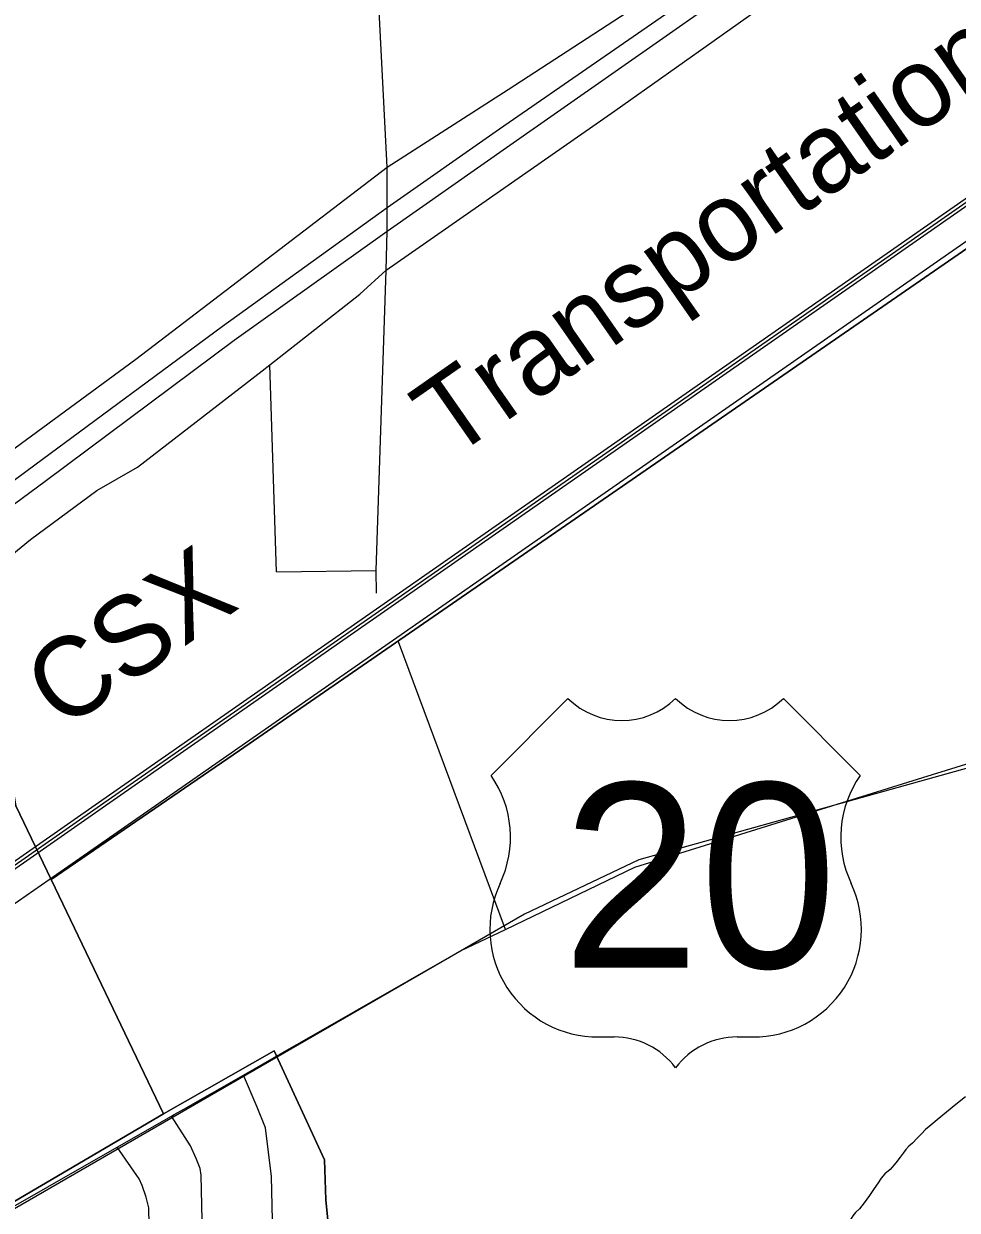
# Model space of a CAD drawing. Extents: x 0 to 44.3, y 0 to 22.
# Drawn here: x 2.7 to 3.367, y 16.867 to 17.715 of the extents above; entities that cross this region are included whole.
import ezdxf

# ---------------------------------------------------------------- set-up
doc = ezdxf.new("R2010")
doc.units = 0
for name, color, linetype in [('GM_X_City_Street', 7, 'Continuous'), ('GM_X_Corporation', 7, 'Continuous'), ('GM_X_County_Road', 7, 'Continuous'), ('GM_X_Minor_River', 7, 'Continuous'), ('GM_X_Rail_Line', 7, 'Continuous'), ('GM_X_Rail_Line_Text', 7, 'Continuous'), ('GM_X_State_Route', 7, 'Continuous'), ('GM_X_US_Location', 7, 'Continuous'), ('GM_X_US_Route', 7, 'Continuous'), ('GM_X_US_Shield', 7, 'Continuous')]:
    doc.layers.add(name, color=color, linetype=linetype)

msp = doc.modelspace()

# ---------------------------------------------------------------- linework, layer by layer
at = {"layer": 'GM_X_City_Street'}
for p, q in [((2.88029, 17.32334), (2.87573, 17.47119)), ((2.88029, 17.32334), (2.95151, 17.32441)), ((3.04389, 17.06804), (2.96757, 17.27355))]:
    msp.add_line(p, q, dxfattribs=at)
for points in [[(2.95187, 17.30811), (2.95151, 17.32441), (2.95874, 17.53886), (2.9594, 17.56671), (2.9594, 17.58355), (2.9594, 17.61233), (2.94193, 17.95676), (2.94104, 18.04987), (2.9488, 18.40637)], [(2.88377, 16.39702), (2.88228, 16.44641), (2.88116, 16.49123), (2.88085, 16.51724), (2.87975, 16.60759), (2.8797, 16.61126), (2.8775, 16.73361), (2.87748, 16.73471), (2.87809, 16.83955), (2.87673, 16.89154), (2.87266, 16.92638), (2.86669, 16.94107), (2.85676, 16.96405)], [(2.83536, 16.49119), (2.83285, 16.60705), (2.83014, 16.73191), (2.82665, 16.89244), (2.826, 16.89737), (2.82305, 16.90437), (2.81901, 16.91356), (2.80533, 16.93467)], [(2.79671, 16.49113), (2.78916, 16.86929), (2.78734, 16.87677), (2.7844, 16.88524), (2.78232, 16.89004), (2.76664, 16.91258)]]:
    msp.add_lwpolyline(points, dxfattribs=at)
at = {"layer": 'GM_X_Corporation'}
for points in [[(2.1, 19.02359), (2.1, 17.10272), (2.42877, 17.10648), (2.43353, 16.7048), (2.48712, 16.74746), (2.538, 16.78285), (2.79959, 16.93639), (2.71939, 17.10372), (2.69423, 17.15622), (2.62885, 17.5345), (2.62195, 17.86014), (2.59129, 17.85933), (2.5903, 17.98005), (2.60997, 17.98184), (2.60886, 18.21609), (2.59413, 18.21561), (2.59648, 18.31022), (2.59485, 18.40033), (2.69521, 18.39964), (2.69153, 18.60222), (2.17836, 19.1187), (2.14854, 19.0743)], [(2.1, 17.10272), (2.1, 14.89093), (2.15007, 14.89026), (2.15156, 14.77637), (2.41649, 14.78874), (2.41538, 14.81071), (2.41193, 15.22884), (3.14802, 15.25348), (3.1444, 15.75035), (3.14473, 15.8221), (3.08208, 15.81996), (3.0702, 16.39939), (3.07041, 16.48664), (2.92509, 16.48168), (2.92043, 16.69656), (2.91923, 16.83909), (2.91562, 16.87504), (2.91478, 16.90347), (2.87873, 16.98136), (2.79959, 16.93639), (2.538, 16.78285), (2.48712, 16.74746), (2.43353, 16.7048), (2.42877, 17.10648)]]:
    msp.add_lwpolyline(points, close=True, dxfattribs=at)
for points in [[(2.62195, 17.86014), (2.62885, 17.5345), (2.69423, 17.15622), (2.71939, 17.10372), (2.85409, 17.19593), (3.47183, 17.62229), (3.84891, 17.88417)], [(3.84891, 17.88417), (3.47183, 17.62229), (2.85409, 17.19593), (2.71939, 17.10372), (2.79959, 16.93639), (2.87873, 16.98136), (2.91478, 16.90347), (2.91562, 16.87504), (2.91923, 16.83909), (2.92043, 16.69656), (2.92509, 16.48168), (3.07041, 16.48664), (3.0702, 16.39939), (3.08208, 15.81996), (3.14473, 15.8221), (3.1444, 15.75035), (3.60768, 15.75757), (3.60129, 15.98668), (3.6481, 15.9878), (3.64433, 16.10299), (3.96366, 16.11374), (4.24297, 16.33163)]]:
    msp.add_lwpolyline(points, dxfattribs=at)
at = {"layer": 'GM_X_County_Road'}
for points in [[(2.64682, 17.37774), (2.78002, 17.47526), (2.9594, 17.61233), (3.04577, 17.66789), (3.24836, 17.79983)], [(2.66847, 17.31708), (2.70468, 17.34646), (2.75217, 17.38143), (2.78106, 17.39808), (2.87021, 17.46686), (2.87573, 17.47119), (2.94001, 17.52169), (2.95874, 17.53886), (3.12202, 17.65265), (3.27527, 17.76142), (3.30285, 17.78047), (3.31643, 17.78986)]]:
    msp.add_lwpolyline(points, dxfattribs=at)
at = {"layer": 'GM_X_Minor_River'}
for points in [[(3.37234, 16.94848), (3.36561, 16.94304), (3.35215, 16.93216), (3.34767, 16.92828), (3.34393, 16.92518)], [(3.34393, 16.92518), (3.34096, 16.92208), (3.33798, 16.91899), (3.33463, 16.91551), (3.33202, 16.91318), (3.32978, 16.91086), (3.32794, 16.90817), (3.32571, 16.90547), (3.32275, 16.90124), (3.31867, 16.89661), (3.31493, 16.8935), (3.31233, 16.89041), (3.31012, 16.88696), (3.30716, 16.8831), (3.30384, 16.8781), (3.30014, 16.87272), (3.29681, 16.86848), (3.29382, 16.86577), (3.29197, 16.86345), (3.29087, 16.86153), (3.28865, 16.85846), (3.28643, 16.85538), (3.28643, 16.85538), (3.28644, 16.855)]]:
    msp.add_lwpolyline(points, dxfattribs=at)
at = {"layer": 'GM_X_Rail_Line'}
for points in [[(5.03994, 18.12339), (4.88582, 17.82603), (4.85215, 17.78603), (4.65574, 17.58324), (4.63259, 17.56921), (3.85279, 17.33195), (3.39071, 17.18793), (3.13922, 17.11763), (3.05755, 17.07901), (2.5475, 16.78444), (2.47772, 16.74057), (2.40462, 16.66842), (2.31181, 16.57815), (2.1, 16.36664)], [(2.1, 16.67388), (2.15394, 16.71136), (2.72349, 17.1075), (3.49807, 17.64675), (4.11147, 18.07403)], [(2.1, 16.70485), (2.10477, 16.70818), (2.37473, 16.89595), (2.52212, 16.99726), (2.7533, 17.15857), (2.93608, 17.28602), (3.53153, 17.70081), (3.67855, 17.8033)], [(2.1, 16.70202), (2.1061, 16.70628), (2.37606, 16.89405), (2.52344, 16.99535), (2.75464, 17.15667), (2.93742, 17.28412), (3.53286, 17.69891), (3.67991, 17.80142)], [(2.1, 16.69919), (2.10744, 16.70438), (2.37739, 16.89214), (2.52477, 16.99345), (2.75597, 17.15477), (2.93875, 17.28222), (3.53419, 17.69701), (3.68127, 17.79954)]]:
    msp.add_lwpolyline(points, dxfattribs=at)
at = {"layer": 'GM_X_State_Route'}
for points in [[(2.59773, 17.31844), (2.70783, 17.39981), (2.84185, 17.49896), (2.9594, 17.58355), (3.03968, 17.63975), (3.18447, 17.74008), (3.35307, 17.85775), (3.41635, 17.90169), (3.50141, 17.96143), (3.50975, 17.96729), (3.59561, 18.02642)], [(2.69326, 17.3719), (2.71528, 17.38818), (2.85017, 17.48885), (2.9594, 17.56671), (3.04713, 17.62812), (3.1952, 17.7316), (3.36215, 17.84725)]]:
    msp.add_lwpolyline(points, dxfattribs=at)
at = {"layer": 'GM_X_US_Route'}
for points in [[(3.34208, 17.17655), (3.38949, 17.19133), (3.39885, 17.19427)], [(2.89868, 16.98798), (3.01231, 17.05289), (3.04389, 17.06804), (3.13631, 17.1124), (3.34208, 17.17655)], [(2.81415, 16.93971), (2.85676, 16.96405), (2.89275, 16.98459), (2.89868, 16.98798)], [(2.45405, 16.71778), (2.4936, 16.7519), (2.54941, 16.78574), (2.62798, 16.83338), (2.66731, 16.85584), (2.76664, 16.91258), (2.80533, 16.93467), (2.80733, 16.93581), (2.81415, 16.93971)]]:
    msp.add_lwpolyline(points, dxfattribs=at)
at = {"layer": 'GM_X_US_Shield'}
for p, q in [((3.08855, 17.23296), (3.03362, 17.17803)), ((3.29729, 17.17803), (3.24236, 17.23296)), ((3.11052, 16.99126), (3.12151, 16.99126)), ((3.2094, 16.99126), (3.22039, 16.99126))]:
    msp.add_line(p, q, dxfattribs=at)
for centre, radius, start, end in [((3.127, 17.27219), 0.05493, 225.573, 314.427), ((3.20391, 17.27219), 0.05493, 225.573, 314.427), ((2.97062, 17.13391), 0.0769, 334.54712, 35.00093), ((3.36029, 17.13391), 0.0769, 144.99907, 205.45288), ((3.10967, 17.06816), 0.0769, 154.83192, 270.63826), ((3.22124, 17.06816), 0.0769, 269.36174, 25.16808), ((3.12151, 16.93633), 0.05493, 36.8699, 90), ((3.2094, 16.93633), 0.05493, 90, 143.1301)]:
    msp.add_arc(centre, radius, start, end, dxfattribs=at)

# ---------------------------------------------------------------- texts
at = {"layer": 'GM_X_Rail_Line_Text'}
for s, height, rotation, p in [('Transportation,', 0.0566288, 34.85466, (3.00464, 17.40299)), ('CSX', 0.056629, 34.79613, (2.72738, 17.20941))]:
    msp.add_text(s, height=height, rotation=rotation, dxfattribs=at).set_placement(p)
at = {"layer": 'GM_X_US_Location'}
for s, p in [('0', (3.16538, 17.10557)), ('/', (3.1654, 17.10557))]:
    msp.add_text(s, height=0.000189, dxfattribs=at).set_placement(p)
msp.add_text('20', height=0.000189, rotation=0.00001, dxfattribs=at).set_placement((3.12629, 17.06637))
at = {"layer": 'GM_X_US_Shield'}
msp.add_text('20', height=0.131836, dxfattribs=at).set_placement((3.08455, 17.0407))

doc.saveas('drawing.dxf')
